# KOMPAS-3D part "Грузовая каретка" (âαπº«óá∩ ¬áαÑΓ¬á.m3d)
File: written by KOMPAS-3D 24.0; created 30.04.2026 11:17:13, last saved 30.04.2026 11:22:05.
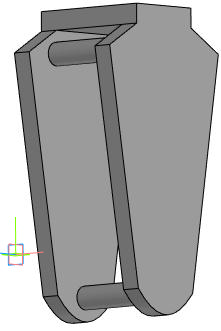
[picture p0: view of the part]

Document properties: Автор: USG_411; Полное имя файла: C:\Users\USG_411\Desktop\ИА-2904_411-12\Балка\Грузовая каретка.m3d

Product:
- Part/product: Грузовая каретка
    Масса: 203.4826

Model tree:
1. Эскиз:1
2. Элемент выдавливания:1
     Расстояние 1 = 323
3. Эскиз:2  (with: Ребро.Элемент выдавливания:1)
4. Элемент выдавливания:2
5. Эскиз:3  (with: Грань.Элемент выдавливания:1, Ребро.Элемент выдавливания:1)
6. Элемент выдавливания:3
     Расстояние 1 = 50
7. Эскиз:4  (with: Грань.Элемент выдавливания:1)
8. Элемент выдавливания:4
9. Эскиз:5  (with: Грань.Элемент выдавливания:1)
10. Элемент выдавливания:5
